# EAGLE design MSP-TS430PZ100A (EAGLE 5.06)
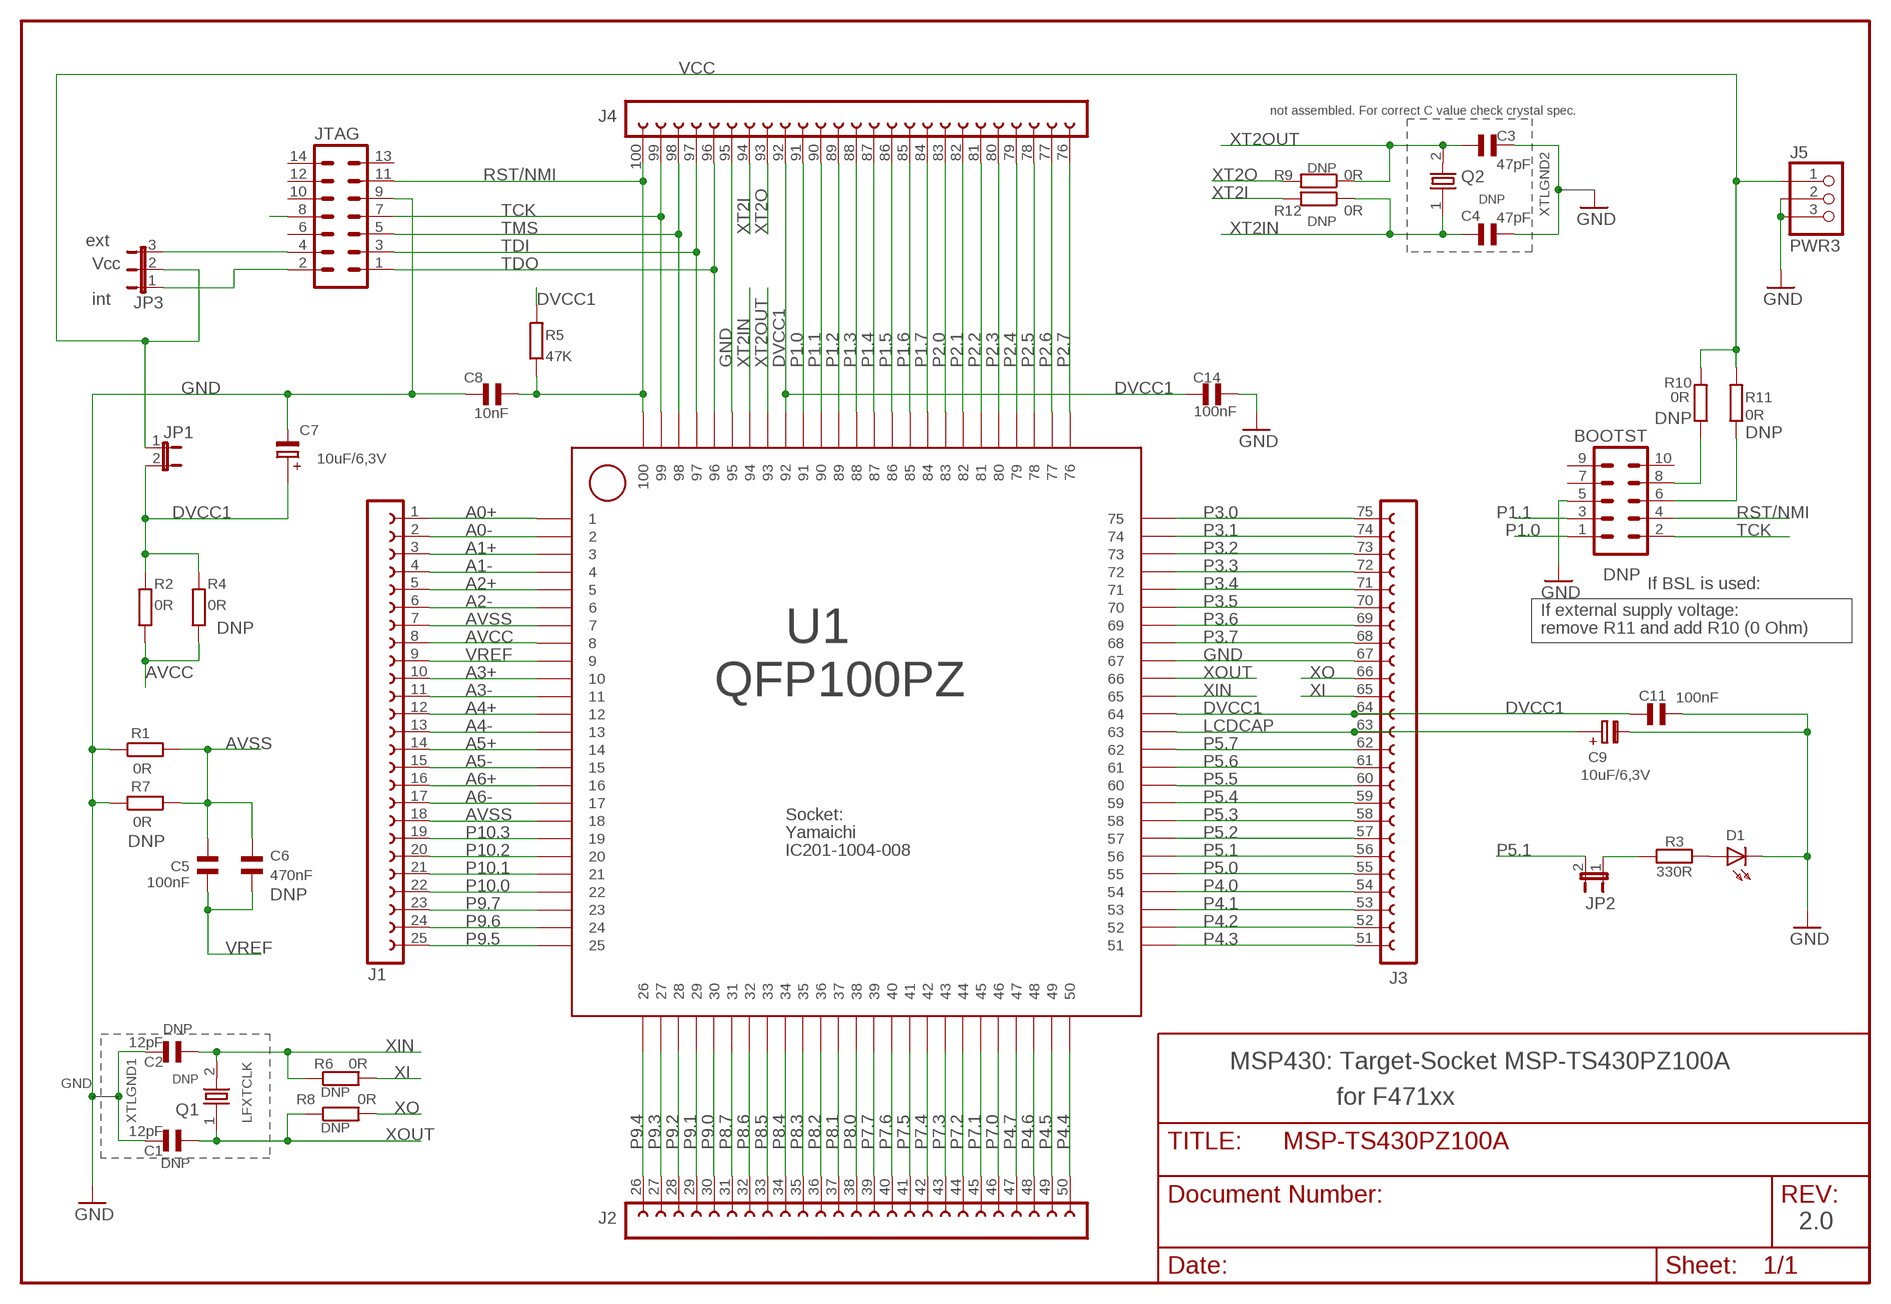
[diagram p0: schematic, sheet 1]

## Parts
BOOTST  ML10  [ML10]
C1  12pF  CSMD0805  [CSMD0805]
C2  12pF  CSMD0805  [CSMD0805]
C3  47pF  CSMD0805  [CSMD0805]
C4  47pF  CSMD0805  [CSMD0805]
C5  100nF  CSMD0805  [CSMD0805]
C6  470nF  CSMD0805  [CSMD0805]
C7  10uF/6,3V  ELKO_1210  [1210ELKO]
C8  10nF  CSMD0805  [CSMD0805]
C9  10uF/6,3V  ELKO_1210  [1210ELKO]
C11  100nF  CSMD0805  [CSMD0805]
C14  100nF  CSMD0805  [CSMD0805]
D1  LED30805  [DIODE_0805]
J1  FE25-1A1  [FE25-1A1]
J2  FE25-1A2  [FE25-1A2]
J3  FE25-1A3  [FE25-1A3]
J4  FE25-1A4  [FE25-1A4]
J5  PWR3  [PWR3]
JP1  JP1E  [JP1]
JP2  JP1E  [JP1]
JP3  JP2ESMALLPAD  [JP2Z]
JTAG  ML14  [ML14]
Q1  HCTC_XTLTCV  [TCV]
Q2  HCTC_XTLTCV  [TCV]
R1  0R  R_0805  [0805]
R2  0R  R_0805  [0805]
R3  330R  R_0805  [0805]
R4  0R  R_0805  [0805]
R5  47K  R_0805  [0805]
R6  0R  R_0805  [0805]
R7  0R  R_0805  [0805]
R8  0R  R_0805  [0805]
R9  0R  R_0805  [0805]
R10  0R  R_0805  [0805]
R11  0R  R_0805  [0805]
R12  0R  R_0805  [0805]
U1  QFP100PZ  [QFP100PZ]

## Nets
A0+: J1.1 U1.P1
A0-: J1.2 U1.P2
A1+: J1.3 U1.P3
A1-: J1.4 U1.P4
A2+: J1.5 U1.P5
A2-: J1.6 U1.P6
A3+: J1.10 U1.P10
A3-: J1.11 U1.P11
A4+: J1.12 U1.P12
A4-: J1.13 U1.P13
A5+: J1.14 U1.P14
A5-: J1.15 U1.P15
A6+: J1.16 U1.P16
A6-: J1.17 U1.P17
AVCC: J1.8 R2.1 R4.1 U1.P8
AVSS: C5.1 C6.1 J1.7 J1.18 R1.2 R7.2 U1.P7 U1.P18
DVCC1: C7.+ C11.1 C14.2 J3.64 J4.92 JP1.2 R2.2 R4.2 R5.2 U1.P64 U1.P92
GND: BOOTST.5 C7.- C8.1 C9.- C11.2 C14.1 D1.K J3.67 J4.95 J5.2 J5.3 JTAG.9 R1.1 R7.1 U1.P67 U1.P95
LCDCAP: C9.+ J3.63 U1.P63
N$1: JP2.1 R3.2
N$7: JP3.1 JTAG.2
N$18: D1.A R3.1
N$23: JP3.3 JTAG.4
N$27: JTAG.8
N$42: BOOTST.8 R10.1
N$49: BOOTST.6 R11.1
P1.0: BOOTST.1 J4.91 U1.P91
P1.1: BOOTST.3 J4.90 U1.P90
P1.2: J4.89 U1.P89
P1.3: J4.88 U1.P88
P1.4: J4.87 U1.P87
P1.5: J4.86 U1.P86
P1.6: J4.85 U1.P85
P1.7: J4.84 U1.P84
P2.0: J4.83 U1.P83
P2.1: J4.82 U1.P82
P2.2: J4.81 U1.P81
P2.3: J4.80 U1.P80
P2.4: J4.79 U1.P79
P2.5: J4.78 U1.P78
P2.6: J4.77 U1.P77
P2.7: J4.76 U1.P76
P3.0: J3.75 U1.P75
P3.1: J3.74 U1.P74
P3.2: J3.73 U1.P73
P3.3: J3.72 U1.P72
P3.4: J3.71 U1.P71
P3.5: J3.70 U1.P70
P3.6: J3.69 U1.P69
P3.7: J3.68 U1.P68
P4.0: J3.54 U1.P54
P4.1: J3.53 U1.P53
P4.2: J3.52 U1.P52
P4.3: J3.51 U1.P51
P4.4: J2.50 U1.P50
P4.5: J2.49 U1.P49
P4.6: J2.48 U1.P48
P4.7: J2.47 U1.P47
P5.0: J3.55 U1.P55
P5.1: J3.56 JP2.2 U1.P56
P5.2: J3.57 U1.P57
P5.3: J3.58 U1.P58
P5.4: J3.59 U1.P59
P5.5: J3.60 U1.P60
P5.6: J3.61 U1.P61
P5.7: J3.62 U1.P62
P7.0: J2.46 U1.P46
P7.1: J2.45 U1.P45
P7.2: J2.44 U1.P44
P7.3: J2.43 U1.P43
P7.4: J2.42 U1.P42
P7.5: J2.41 U1.P41
P7.6: J2.40 U1.P40
P7.7: J2.39 U1.P39
P8.0: J2.38 U1.P38
P8.1: J2.37 U1.P37
P8.2: J2.36 U1.P36
P8.3: J2.35 U1.P35
P8.4: J2.34 U1.P34
P8.5: J2.33 U1.P33
P8.6: J2.32 U1.P32
P8.7: J2.31 U1.P31
P9.0: J2.30 U1.P30
P9.1: J2.29 U1.P29
P9.2: J2.28 U1.P28
P9.3: J2.27 U1.P27
P9.4: J2.26 U1.P26
P9.5: J1.25 U1.P25
P9.6: J1.24 U1.P24
P9.7: J1.23 U1.P23
P10.0: J1.22 U1.P22
P10.1: J1.21 U1.P21
P10.2: J1.20 U1.P20
P10.3: J1.19 U1.P19
RST/NMI: BOOTST.4 C8.2 J4.100 JTAG.11 R5.1 U1.P100
TCK: BOOTST.2 J4.99 JTAG.7 U1.P99
TDI: J4.97 JTAG.3 U1.P97
TDO: J4.96 JTAG.1 U1.P96
TMS: J4.98 JTAG.5 U1.P98
VCC: J5.1 JP1.1 JP3.2 R10.2 R11.2
VREF: C5.2 C6.2 J1.9 U1.P9
XI: J3.65 R6.2
XIN: C2.1 Q1.2 R6.1 U1.P65
XO: J3.66 R8.2
XOUT: C1.1 Q1.1 R8.1 U1.P66
XT2I: J4.94 R12.2
XT2IN: C4.1 Q2.1 R12.1 U1.P94
XT2O: J4.93 R9.2
XT2OUT: C3.1 Q2.2 R9.1 U1.P93
XTLGND1: C1.2 C2.2
XTLGND2: C3.2 C4.2
Unconnected: BOOTST.7 BOOTST.9 BOOTST.10 JTAG.6 JTAG.10 JTAG.12 JTAG.13 JTAG.14

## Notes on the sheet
- not assembled. For correct C value check crystal spec.
- DNP
- DNP
- DNP
- ext
- Vcc
- int
- DNP
- DNP
- DNP
- If BSL is used:
- If external supply voltage:
- DNP | remove R11 and add R10 (0 Ohm)
- Socket:
- Yamaichi
- DNP
- IC201-1004-008
- DNP
- DNP
- MSP430: Target-Socket MSP-TS430PZ100A
- DNP
- GND
- DNP
- for F471xx
- LFXTCLK | DNP
- DNP
- 2.0

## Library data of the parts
BOOTST = con-ml:ML10
C1-C6 C8 C11 C14 = cap:CSMD0805
C7 C9 = smd:ELKO_1210
D1 = MSP430:LED3
J1 = CON-LSTA:FE25-1A1
J2 = CON-LSTA:FE25-1A2
J3 = CON-LSTA:FE25-1A3
J4 = CON-LSTA:FE25-1A4
J5 = MSP430:PWR3
JP1 JP2 = jumper:JP1E: JUMPER
JP3 = jumper:JP2E: JUMPER
JTAG = con-ml:ML14
Q1 Q2 = scrystal:HCTC_XTL
R1-R12 = smd:R_0805
U1 = MSP430:QFP100PZ

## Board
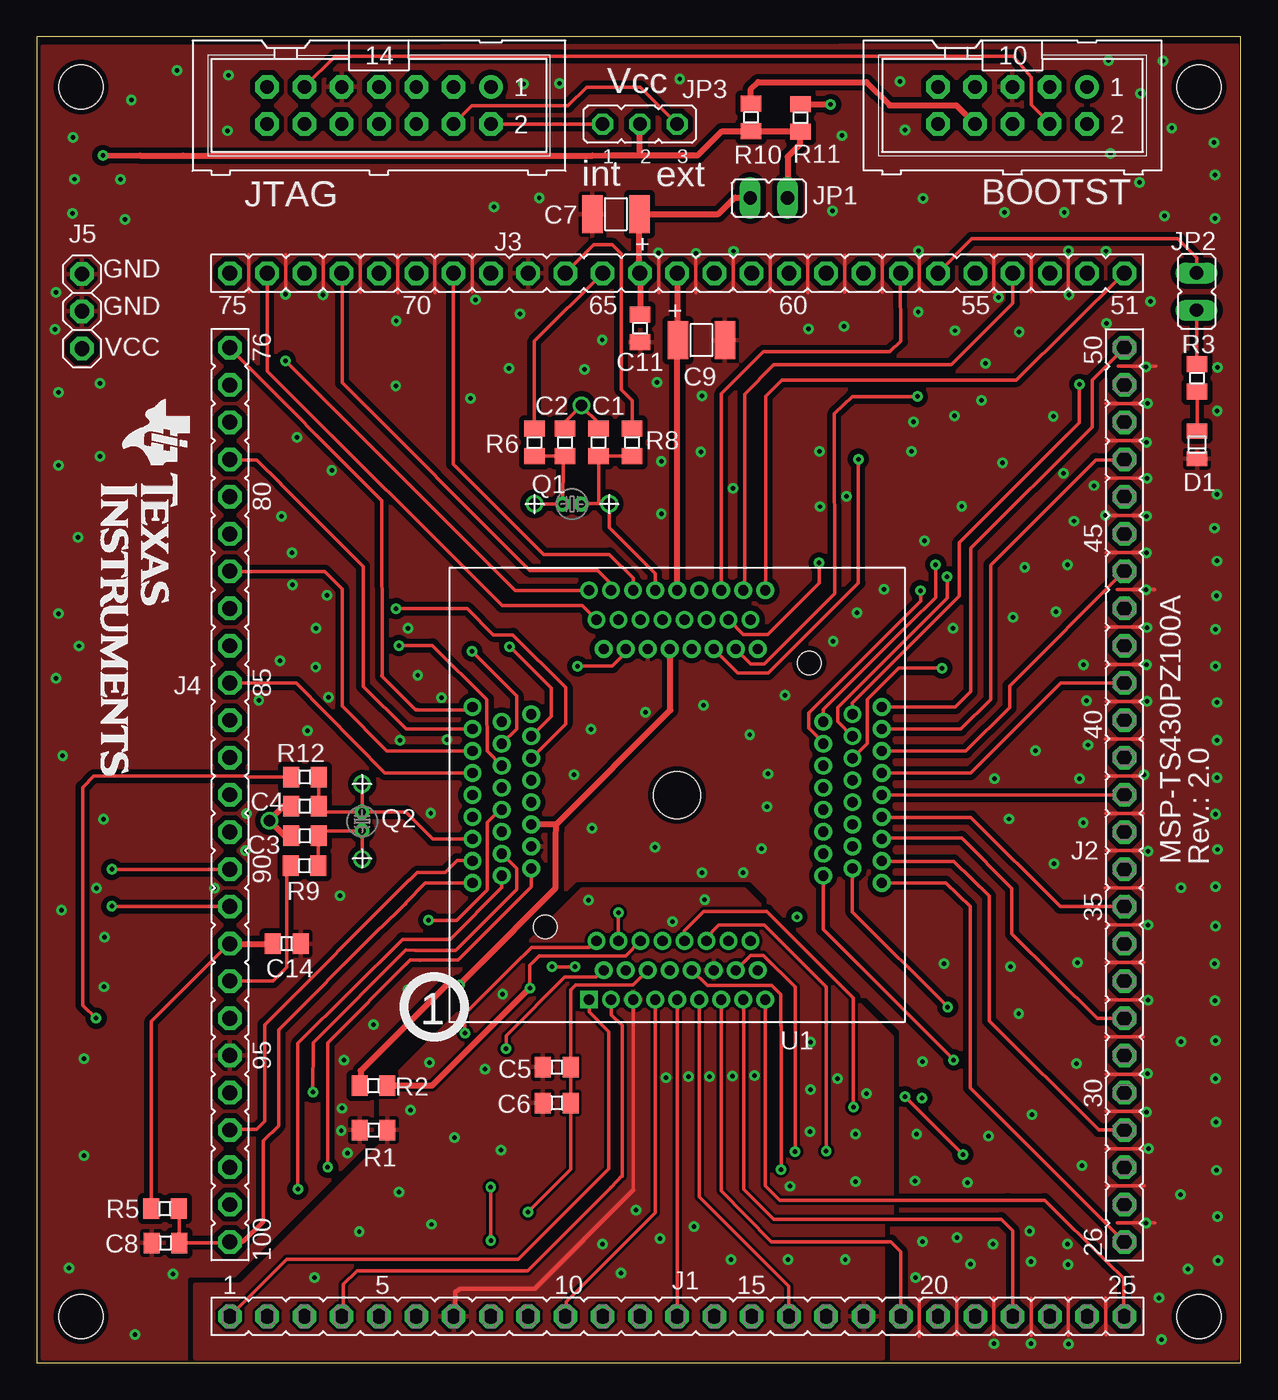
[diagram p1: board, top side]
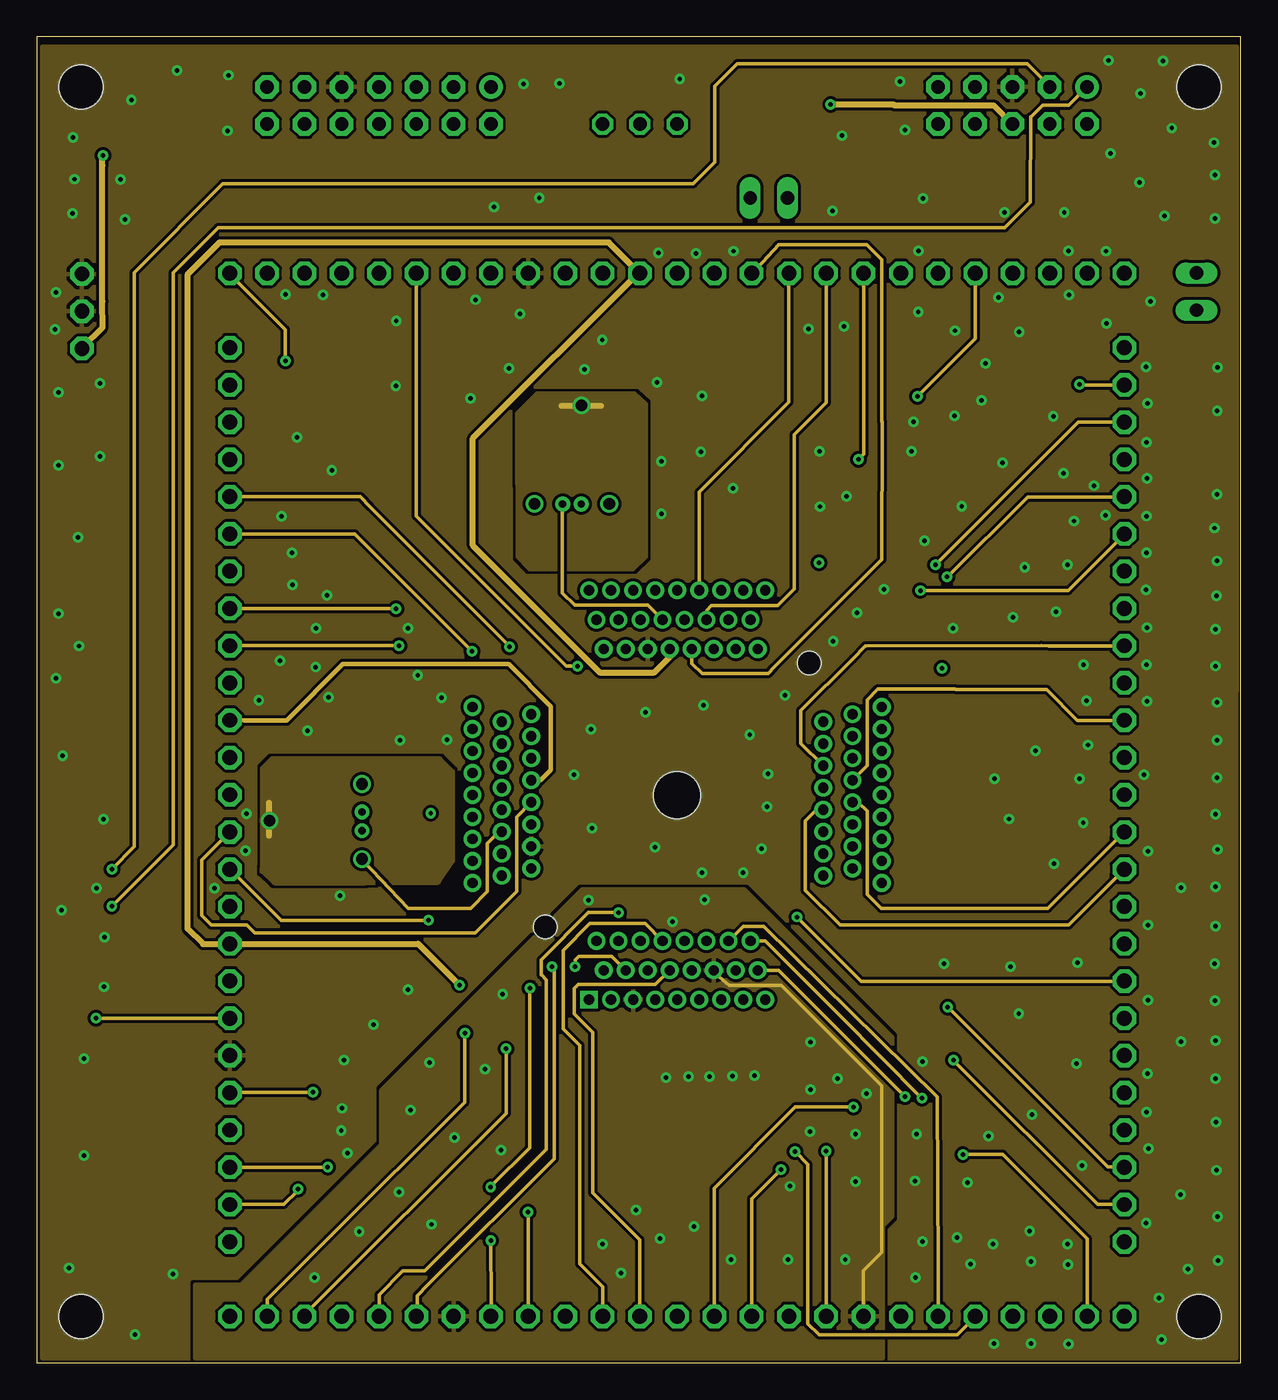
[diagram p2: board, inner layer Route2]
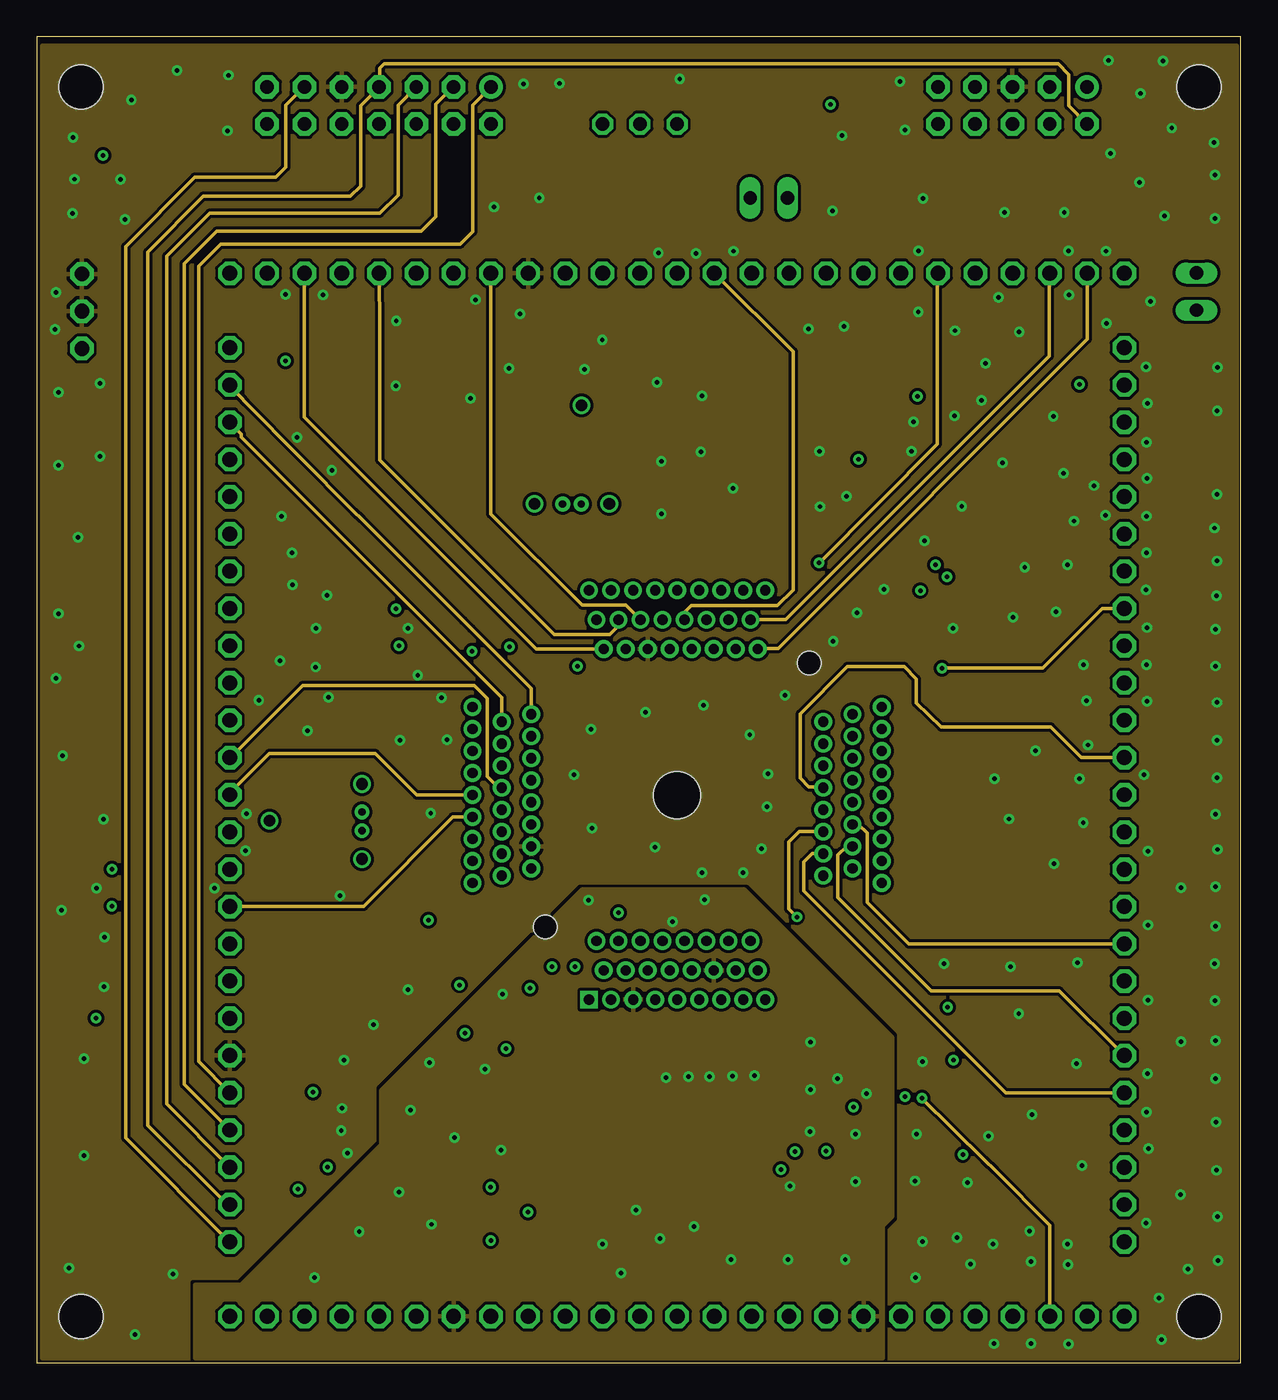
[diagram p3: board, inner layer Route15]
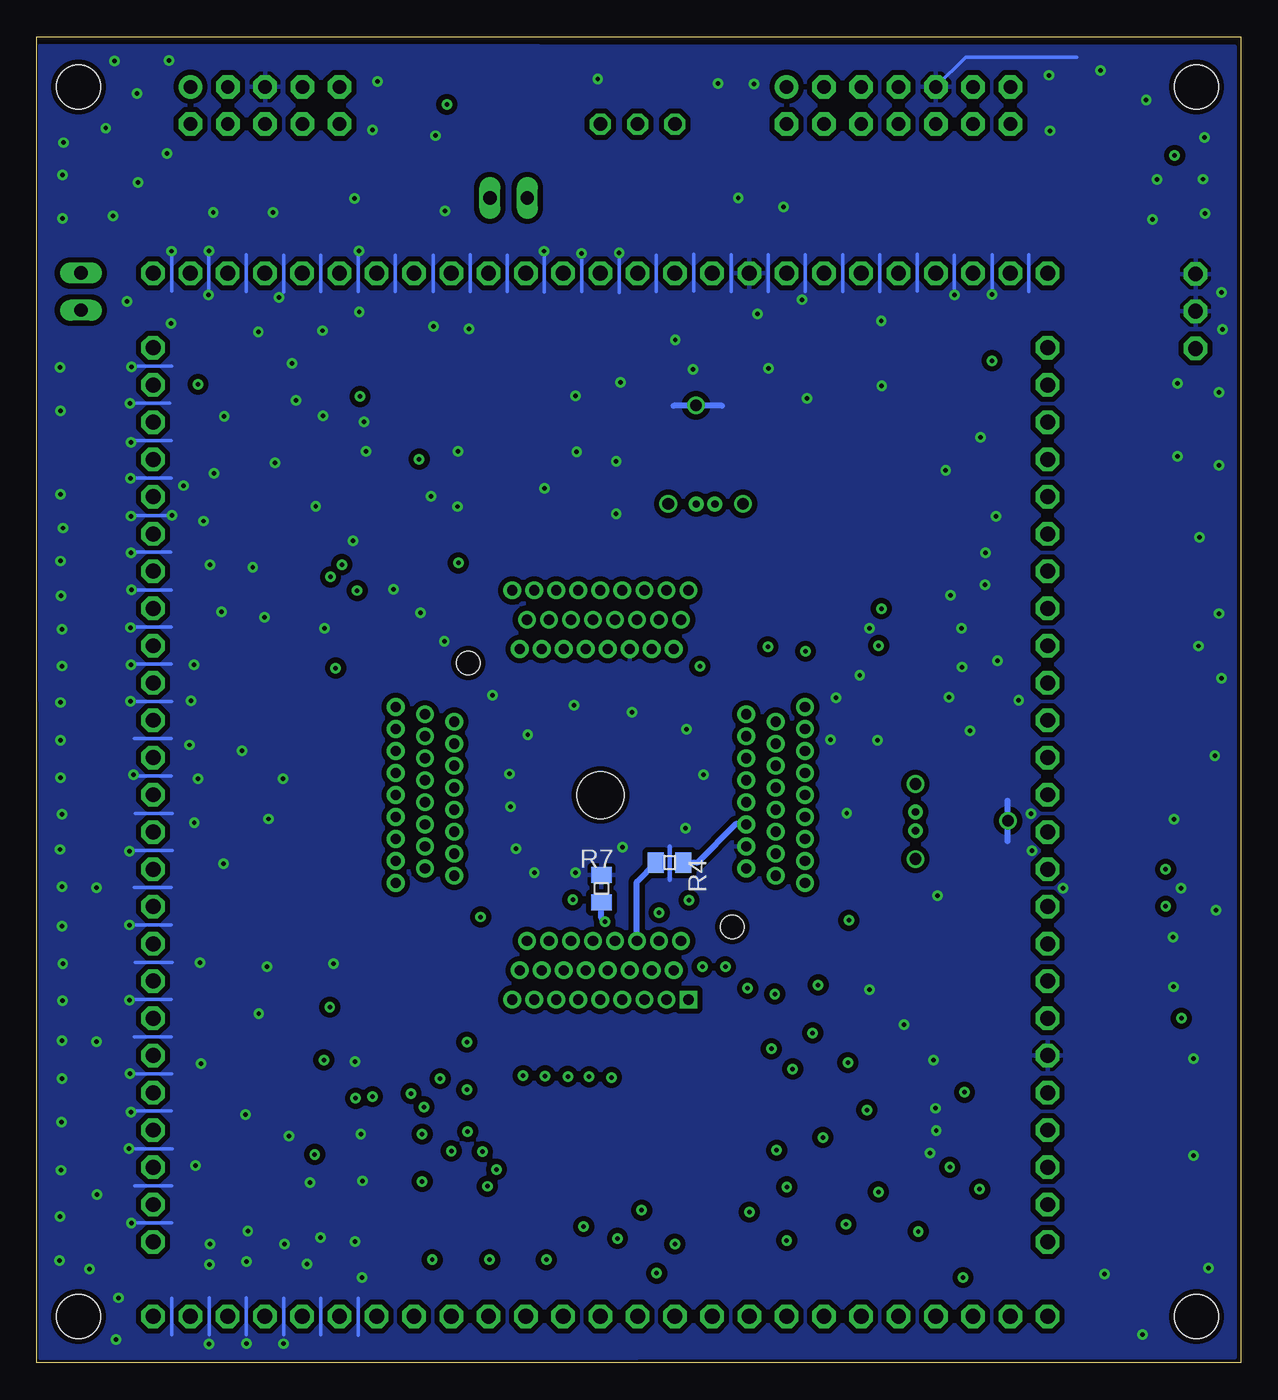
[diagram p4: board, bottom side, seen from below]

Size 82.07 x 90.41 mm. Coordinates in mm from the lower left corner, seen from the top.
Outline: 0,0 82.06,0 82.06,90.41 0,90.41 0,0
Copper layers (1*2+15*16): Top 0.035mm / dielectric 1.5mm / Route2 0.035mm / dielectric 1.5mm / Route15 0.035mm / dielectric 1.5mm / Bottom 0.035mm
Design rules "default *": minimum track width 8mil, minimum drill 12mil, track to track 8mil, track to pad 8mil, pad to pad 8mil, via to via 8mil, smd to smd 8mil, copper to edge 0mil, drill to drill 8mil, minimum pad ring 10mil, minimum via ring 8mil, stop-mask expansion 0mil, vias tented up to drill 0mil, thermal gap 10mil
Holes 3 mm at 3.01,3.17 3.01,86.99 79.21,3.17 79.21,86.99
tRestrict: 2 lines
bRestrict: 2 lines

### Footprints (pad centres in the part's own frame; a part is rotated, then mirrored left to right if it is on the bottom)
ML10 = drill 0.914 pad 1.6 round: 1 -5.08,-1.27 | drill 0.914 pad 1.6 octagon: 2 -5.08,1.27; 3 -2.54,-1.27; 4 -2.54,1.27; 5 0,-1.27; 6 0,1.27; 7 2.54,-1.27; 8 2.54,1.27; 9 5.08,-1.27; 10 5.08,1.27
CSMD0805 = smd 1.092 x 1.397: 1 -0.94,0; 2 0.94,0
1210ELKO = smd 1.397 x 2.591: + 1.6,0; - -1.6,0
DIODE_0805 = smd 1 x 1.4: A -0.94,0; K 0.94,0
FE25-1A1 = drill 1.016 pad 1.6 octagon: 1 -30.48,0; 2 -27.94,0; 3 -25.4,0; 4 -22.86,0; 5 -20.32,0; 6 -17.78,0; 7 -15.24,0; 8 -12.7,0; 9 -10.16,0; 10 -7.62,0; 11 -5.08,0; 12 -2.54,0; 13 0,0; 14 2.54,0; 15 5.08,0; 16 7.62,0; 17 10.16,0; 18 12.7,0; 19 15.24,0; 20 17.78,0; 21 20.32,0; 22 22.86,0; 23 25.4,0; 24 27.94,0; 25 30.48,0
FE25-1A2 = drill 1.016 pad 1.6 octagon: 26 -30.48,0; 27 -27.94,0; 28 -25.4,0; 29 -22.86,0; 30 -20.32,0; 31 -17.78,0; 32 -15.24,0; 33 -12.7,0; 34 -10.16,0; 35 -7.62,0; 36 -5.08,0; 37 -2.54,0; 38 0,0; 39 2.54,0; 40 5.08,0; 41 7.62,0; 42 10.16,0; 43 12.7,0; 44 15.24,0; 45 17.78,0; 46 20.32,0; 47 22.86,0; 48 25.4,0; 49 27.94,0; 50 30.48,0
FE25-1A3 = drill 1.016 pad 1.6 octagon: 51 -30.48,0; 52 -27.94,0; 53 -25.4,0; 54 -22.86,0; 55 -20.32,0; 56 -17.78,0; 57 -15.24,0; 58 -12.7,0; 59 -10.16,0; 60 -7.62,0; 61 -5.08,0; 62 -2.54,0; 63 0,0; 64 2.54,0; 65 5.08,0; 66 7.62,0; 67 10.16,0; 68 12.7,0; 69 15.24,0; 70 17.78,0; 71 20.32,0; 72 22.86,0; 73 25.4,0; 74 27.94,0; 75 30.48,0
FE25-1A4 = drill 1.016 pad 1.6 octagon: 76 -30.48,0; 77 -27.94,0; 78 -25.4,0; 79 -22.86,0; 80 -20.32,0; 81 -17.78,0; 82 -15.24,0; 83 -12.7,0; 84 -10.16,0; 85 -7.62,0; 86 -5.08,0; 87 -2.54,0; 88 0,0; 89 2.54,0; 90 5.08,0; 91 7.62,0; 92 10.16,0; 93 12.7,0; 94 15.24,0; 95 17.78,0; 96 20.32,0; 97 22.86,0; 98 25.4,0; 99 27.94,0; 100 30.48,0
PWR3 = drill 1.016 pad 1.6 octagon: 1 -2.54,0; 2 0,0; 3 2.54,0
JP1 = drill 0.914 long: 1 0,-1.27; 2 0,1.27
JP2Z = drill 0.914 octagon: 1 -2.54,0; 2 0,0; 3 2.54,0
ML14 = drill 0.914 pad 1.6 round: 1 -7.62,-1.27 | drill 0.914 pad 1.6 octagon: 2 -7.62,1.27; 3 -5.08,-1.27; 4 -5.08,1.27; 5 -2.54,-1.27; 6 -2.54,1.27; 7 0,-1.27; 8 0,1.27; 9 2.54,-1.27; 10 2.54,1.27; 11 5.08,-1.27; 12 5.08,1.27; 13 7.62,-1.27; 14 7.62,1.27
TCV = drill 0.5 round: 1 -0.635,0; 2 0.635,0
0805 = smd 1.092 x 1.397: 1 -0.94,0; 2 0.94,0
QFP100PZ = drill 0.7 pad 1 square: P1 -6,-13.95 | drill 0.7 pad 1 round: P2 -5.5,-9.95; P3 -5,-11.95; P4 -4.5,-13.95; P5 -4,-9.95; P6 -3.5,-11.95; P7 -3,-13.95; P8 -2.5,-9.95; P9 -2,-11.95; P10 -1.5,-13.95; P11 -1,-9.95; P12 -0.5,-11.95; P13 0,-13.95; P14 0.5,-9.95; P15 1,-11.95; P16 1.5,-13.95; P17 2,-9.95; P18 2.5,-11.95; P19 3,-13.95; P20 3.5,-9.95; P21 4,-11.95; P22 4.5,-13.95; P23 5,-9.95; P24 5.5,-11.95; P25 6,-13.95; P26 13.95,-6; P27 9.95,-5.5; P28 11.95,-5; P29 13.95,-4.5; P30 9.95,-4; P31 11.95,-3.5; P32 13.95,-3; P33 9.95,-2.5; P34 11.95,-2; P35 13.95,-1.5; P36 9.95,-1; P37 11.95,-0.5; P38 13.95,0; P39 9.95,0.5; P40 11.95,1; P41 13.95,1.5; P42 9.95,2; P43 11.95,2.5; P44 13.95,3; P45 9.95,3.5; P46 11.95,4; P47 13.95,4.5; P48 9.95,5; P49 11.95,5.5; P50 13.95,6; P51 6,13.95; P52 5.5,9.95; P53 5,11.95; P54 4.5,13.95; P55 4,9.95; P56 3.5,11.95; P57 3,13.95; P58 2.5,9.95; P59 2,11.95; P60 1.5,13.95; P61 1,9.95; P62 0.5,11.95; P63 0,13.95; P64 -0.5,9.95; P65 -1,11.95; P66 -1.5,13.95; P67 -2,9.95; P68 -2.5,11.95; P69 -3,13.95; P70 -3.5,9.95; P71 -4,11.95; P72 -4.5,13.95; P73 -5,9.95; P74 -5.5,11.95; P75 -6,13.95; P76 -13.95,6; P77 -9.95,5.5; P78 -11.95,5; P79 -13.95,4.5; P80 -9.95,4; P81 -11.95,3.5; P82 -13.95,3; P83 -9.95,2.5; P84 -11.95,2; P85 -13.95,1.5; P86 -9.95,1; P87 -11.95,0.5; P88 -13.95,0; P89 -9.95,-0.5; P90 -11.95,-1; P91 -13.95,-1.5; P92 -9.95,-2; P93 -11.95,-2.5; P94 -13.95,-3; P95 -9.95,-3.5; P96 -11.95,-4; P97 -13.95,-4.5; P98 -9.95,-5; P99 -11.95,-5.5; P100 -13.95,-6 | hole 3.2: 0,0 | hole 1.6: -9,-9; 9,9

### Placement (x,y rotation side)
BOOTST  66.5,85.72 180 top
C1  38.3,62.77 90 top
C2  36.02,62.76 90 top
C3  18.29,35.93 180 top
C4  18.29,37.95 180 top
C5  35.45,20.16 0 top
C6  35.45,17.72 0 top
C7  39.48,78.33 0 top
C8  8.77,8.18 0 top
C9  45.3,69.72 180 top
C11  41.13,70.54 270 top
C14  17.04,28.58 180 top
D1  79.08,62.58 270 top
J1  43.65,3.17 0 top
J2  74.13,38.73 90 top
J3  43.65,74.29 180 top
J4  13.17,38.73 270 top
J5  3.09,71.7 90 top
JP1  49.9,79.42 90 top
JP2  79.05,73.04 0 top
JP3  41.11,84.45 0 top
JTAG  23.33,85.72 180 top
Q1  36.48,58.55 180 top
Q2  22.17,36.92 270 top
R1  22.96,15.87 0 top
R2  22.97,18.89 180 top
R3  79.09,67.15 90 top
R4  38.93,34.11 0 bottom
R5  8.75,10.51 180 top
R6  33.92,62.75 90 top
R7  43.57,32.33 270 bottom
R8  40.58,62.76 90 top
R9  18.26,33.9 180 top
R10  48.68,84.91 270 top
R11  52.06,84.87 270 top
R12  18.28,39.94 180 top
U1  43.65,38.71 0 top
U$1  [LABEL_2008_TNAMES]  6.31,56.81 270 top

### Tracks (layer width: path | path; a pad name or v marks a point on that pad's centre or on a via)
A0+
  Top 0.254: U1.P1 37.65,23.91 38.99,22.57 38.99,13.23 32.81,7.05 17.06,7.05 13.2,3.2 13.2,3.17 J1.1
A0-  (via drill 0.3)
  Top 0.254: U1.P2 38.17,28.74 38.17,28.73 38.07,28.73 37.66,28.33 33.73,28.33 32.45,27.06 32.45,27.05 29.15,23.75 v29.18,22.48
  Route2 0.254: v29.18,22.48 29.18,17.77 19.83,8.44 15.71,4.32 J1.2
A1+  (via drill 0.3)
  Top 0.254: U1.P3 38.13,26.3 35.99,26.3 31.99,22.31 v31.99,21.41
  Route2 0.254: v31.99,21.41 31.99,20.1 32,19.51 32,17.03 18.27,3.3 18.27,3.19 J1.3
A1-
  Top 0.254: J1.4 20.9,3.3 20.9,5.35 21.83,6.28 33.48,6.28 39.15,11.95 39.14,11.95 39.14,11.96 39.15,11.97 39.89,12.73 39.9,12.72 39.9,22.99 39.16,23.74 39.16,24.31 U1.P4 | J1.4
A2+  (via drill 0.3)
  Top 0.254: U1.P5 39.65,28.74 39.64,28.73 v39.64,30.69
  Route2 0.254: J1.5 23.33,4.64 24.96,6.27 26.46,6.27 34.71,14.55 34.73,26.12 34.38,26.47 34.4,26.45 34.4,27.47 37.58,30.7 38.47,30.7 v39.64,30.69
A2-  (via drill 0.3)
  Top 0.254: v35.13,27 v36.7,27
  Route2 0.254: U1.P6 39.19,27.72 36.95,27.72 36.7,27.46 v36.7,27 | v35.13,27 35.27,26.83 35.27,13.91 26.7,5.34 25.94,4.59 25.95,3.9 25.89,3.85 25.89,3.19 J1.6
A3+
  Top 0.254: 35.9,3.17 35.85,3.12 | 35.9,3.17 J1.10 | 35.9,3.17 36.1,3.37 36.1,4.17 42.15,10.22 U1.P10
A3-
  Route2 0.254: U1.P11 41.47,29.94 37.71,29.94 35.88,28.11 35.88,22.75 36.99,21.64 36.99,6.75 38.57,5.18 J1.11
A4+
  Route2 0.254: U1.P12 42.17,25.79 36.9,25.79 36.65,25.53 36.65,23.79 37.91,22.52 37.91,19.83 37.89,19.42 37.91,19.08 37.91,11.6 41.11,8.37 J1.12
A4-
  Top 0.254: J1.13 U1.P13
A5+  (via drill 0.3)
  Top 0.254: U1.P14 44.15,29.45 45.48,30.78 49.77,30.78 55.66,24.89 v55.66,17.45
  Route2 0.254: v55.66,17.45 51.7,17.45 46.16,11.91 46.16,4.11 46.19,3.75 J1.14
A5-  (via drill 0.3)
  Top 0.254: U1.P15 45.69,25.72 50.11,25.72 50.72,25.12 50.72,23 50.73,22.99 v50.73,13.19
  Route2 0.254: J1.15 48.73,4.31 48.73,11.19 v50.73,13.19
A6+
  Top 0.254: U1.P16 45.15,11.32 51.27,5.2 J1.16
A6-  (via drill 0.3)
  Top 0.254: v53.81,14.45 53.81,25.62 49.59,29.84 46.5,29.84 45.61,28.95 45.65,28.91 U1.P17
  Route2 0.254: J1.17 v53.81,14.45
AVCC  (via drill 0.3)
  Top 0.254: U1.P8 40.14,27.75 34.25,27.75 34.25,27.74 33.78,27.27 33.78,27.26 33.62,27.09 v33.62,25.53 | v30.95,8.35 v30.95,11.99
  Top 0.406: v33.62,25.53 33.58,25.53 26.94,18.89 R2.1
  Route2 0.254: v33.62,25.53 33.62,24.23 33.61,24.02 33.61,14.67 30.96,12.02 v30.95,11.99 | J1.8 30.97,4.11 v30.95,8.35
  Bottom 0.406: U1.P8 41.16,32.79 R4.1
AVSS  (via drill 0.3 pad 0.3)
  Top 0.254: 28.52,3.46 28.35,3.29 28.41,3.23 J1.7 | U1.P7 40.65,24.39 40.65,24.31 40.65,24.21 40.65,11.79
  Top 0.305: 40.65,11.79 33.94,5.06 28.88,5.06 28.52,4.85 28.52,3.46
  Route2 0.254: 46.53,26.3 U1.P18 | 46.53,26.3 U1.P18 | 46.53,26.3 47.19,25.73 50.75,25.73 57.58,18.89 57.58,7.54 56.32,6.27 56.32,4.37 J1.18
  Bottom 0.406: v43.34,30.07 43.34,30.09 43.57,30.32 R7.2
  other vias: 26.91,9.44 31.64,14.5 30.54,20.04 28.49,15.36 24.7,11.65 18.94,5.81 21.98,8.96 25.49,17.24 26.78,20.47 31.76,25.14 37.6,31.54 45.53,31.57 42.89,19.45 44.41,19.5 45.86,19.53 47.41,19.55 48.91,19.58 52.74,21.86 52.74,18.61 52.69,15.77 54.57,19.38 56.55,18.36 55.79,15.59 55.79,12.36 51.35,12.03 44.79,9.29 42.48,8.48 39.81,6.12 38.57,8.1 40.83,10.41 47.33,7.03 51.19,7.03 55.11,7.03
  pour Top: 10.81,5.3 13.93,5.3 23.48,14.85 23.48,18.56 37.2,32.28 48.22,32.28 58.28,22.22 58.28,9.98 57.65,9.34 57.65,0.3 10.81,0.3
  pour Route2: 10.81,5.3 13.93,5.3 23.48,14.85 23.48,18.56 37.2,32.28 48.22,32.28 58.31,22.19 58.31,10 57.65,9.34 57.65,0.33 10.81,0.33
  pour Route15: 10.81,5.3 13.93,5.3 23.48,14.85 23.48,18.56 37.2,32.28 48.22,32.28 58.31,22.19 58.31,10 57.65,9.34 57.65,0.3 10.81,0.3
DVCC1  (via drill 0.3)
  Top 0.254: U1.P92 | 22.09,19.02 22.02,18.96 R2.2 | J4.92 13.14,28.57 13.12,28.59 7.81,23.29 R5.2
  Top 0.406: 35.4,36.7 35.38,35.7 35.38,32.39 29.79,26.76 v28.81,25.76 27.94,25.76 22.09,19.91 22.09,19.02 | 35.4,36.7 34.35,36.72 U1.P92 | C11.1 41.13,74.23 41.13,74.24 41.11,74.27 J3.64 41.11,74.52 41.08,74.55 C7.+ 46.47,78.33 47.59,79.45 48.43,79.45 48.45,79.47 48.5,79.42 JP1.2 | C14.2 J4.92 | U1.P64 43.19,48.62 43.19,44.5 35.4,36.7
  Route2 0.406: J4.92 26,28.57 v28.81,25.76 | U1.P64 43.15,48.14 42.05,47.04 38.42,47.04 29.73,55.72 29.73,63.04 40.98,74.29 J3.64 41.06,74.34 41.03,74.34 39,76.37 12.46,76.37 10.27,74.19 10.27,29.61 11.34,28.54 13.04,28.54
  Bottom 0.406: R4.2 37.05,34.08 34.43,36.72 33.77,36.72 33.76,36.71 U1.P92
GND  (via drill 0.3)
  Top 0.254: 72.86,65.4 75.4,65.4 | 73.72,67.97 76.26,67.97 | 72.94,62.86 75.48,62.86 | 72.89,60.32 75.42,60.32 | 72.96,57.78 75.5,57.78 | 72.91,55.24 75.45,55.24 | 73.65,52.73 76.19,52.73 | 72.89,50.16 75.42,50.16 | 72.94,47.62 75.48,47.62 | 72.91,45.08 75.45,45.08 | 72.83,42.54 75.38,42.54 | 72.89,40.02 75.42,40.02 | 72.86,37.46 75.4,37.46 | 72.89,34.92 75.42,34.92 | 72.83,32.38 75.38,32.38 | 72.96,29.84 75.5,29.84 | 72.91,27.3 75.45,27.3 | 72.89,24.76 75.42,24.76 | 72.86,22.22 75.4,22.22 | 72.89,19.68 75.42,19.68 | 72.89,17.14 75.42,17.14 | 72.91,14.6 75.45,14.6 | 72.94,12.06 75.48,12.06 | 73.65,9.54 76.19,9.54 | 72.86,1.9 72.86,4.44 | 70.32,1.88 70.32,4.41 | 67.78,1.88 67.78,4.41 | 65.24,1.9 65.24,4.44 | 62.7,1.9 62.7,4.44 | 60.16,1.82 60.16,4.36 | 14.44,73.02 14.44,75.56 | 16.98,73.02 16.98,75.56 | 19.52,72.92 19.52,75.46 | 22.06,73 22.06,75.53 | 24.6,72.97 24.6,75.51 | 27.14,72.97 27.14,75.51 | 29.68,73.02 29.68,75.56 | 42.38,72.97 42.38,75.51 | 44.92,72.97 44.92,75.51 | 47.46,73.12 47.46,75.66 | 50,73.02 50,75.56 | 52.54,72.97 52.54,75.51 | 55.08,73 55.08,75.53 | 57.62,73 57.62,75.53 | 60.16,73.07 60.16,75.61 | 65.24,73 65.24,75.53 | 67.78,73.05 67.78,75.59 | 70.32,73.05 70.32,75.59
  Bottom 0.254: JTAG.9 18.75,89.03 11.17,89.03 | v72.86,57.78 75.38,57.78 | 72.94,55.27 75.45,55.27 | 72.91,60.32 75.42,60.32 | 72.91,62.88 75.42,62.88 | 72.89,52.7 75.4,52.7 | 72.89,50.16 75.4,50.16 | 72.91,47.64 75.42,47.64 | 72.86,45.08 75.38,45.08 | 72.89,42.56 75.4,42.56 | 72.89,40.02 75.4,40.02 | 72.83,37.46 75.35,37.46 | 72.83,34.92 75.35,34.92 | 72.91,32.41 75.42,32.41 | 72.91,29.84 75.42,29.84 | 72.83,27.3 75.35,27.3 | 72.89,24.78 75.4,24.78 | 72.89,22.22 75.4,22.22 | 72.86,19.7 75.38,19.7 | 72.89,17.16 75.4,17.16 | 72.83,14.6 75.35,14.6 | 72.86,12.06 75.38,12.06 | 72.86,9.54 75.38,9.54 | 72.86,1.9 72.86,4.41 | 70.32,1.92 70.32,4.44 | 67.78,1.92 67.78,4.44 | 65.24,1.9 65.24,4.41 | 62.7,1.9 62.7,4.41 | 60.14,1.88 60.14,4.39 | 14.44,73.05 14.44,75.56 | 16.95,73.05 16.95,75.56 | 19.52,73.02 19.52,75.53 | 22.06,73.07 22.06,75.59 | 24.6,73.05 24.6,75.56 | 27.14,73.05 27.14,75.56 | 29.68,73.05 29.68,75.56 | 32.22,73.05 32.22,75.56 | 34.73,73.05 34.73,75.56 | 37.3,73.07 37.3,75.59 | 39.84,73.02 39.84,75.53 | 42.35,72.97 42.35,75.48 | 44.92,73.02 44.92,75.53 | 47.46,73 47.46,75.51 | 50,73.02 50,75.53 | 52.52,73.05 52.52,75.56 | 55.05,73.02 55.05,75.53 | 57.62,73.02 57.62,75.53 | 60.16,73.05 60.16,75.56 | 62.7,73.02 62.7,75.53 | 65.24,73 65.24,75.51 | 67.78,73.05 67.78,75.56 | 70.34,73 70.34,75.51 | 72.86,73.07 72.86,75.59 | 73.01,65.42 75.53,65.42 | 72.86,67.94 75.38,67.94
  Bottom 0.305: 38.93,32.91 38.93,35.2
  Bottom 0.406: 35.36,65.25 38.66,65.25 | 15.89,35.58 15.89,38.32
  other vias: 48.6,42.83 53.4,58.38 19.02,47.44 17.44,53.03 19.77,52.32 66.27,37.08 41.49,44.34 60.08,71.64 69.28,64.52 72.06,59.81 47.44,59.61 25.97,46.89 27.58,45.34 29.91,72.48 24.51,71.03 60.37,8.27 59.88,5.83 62.72,8.55 65.17,8.11 63.64,6.74 67.68,8.98 67.76,6.89 63.44,12.28 70.25,8.1 70.3,6.71 64.86,15.47 65.25,1.3 67.77,1.33 70.33,1.27 76.66,1.58 76.49,4.43 75.62,9.52 77.96,11.46 80.41,13.13 80.47,9.97 80.52,6.97 78.46,6.38 59.98,15.58 75.64,17.11 75.78,14.62 80.38,16.4 80.35,19.36 80.35,21.96 75.7,19.7 75.74,24.72 75.74,29.85 80.32,24.69 80.29,27.23 80.35,29.77 60.37,20.55 37.79,43.2 36.62,40.1 45.35,33.43 48.15,33.42 49.41,35.04 49.78,37.92 49.83,40.15 51.01,45.51 45.44,44.82 80.35,32.46 75.75,34.89 80.46,35 80.35,37.4 80.44,39.88 80.44,42.45 80.44,45.02 75.47,40.08 75.67,45.11 75.64,47.59 75.67,50.13 75.61,52.7 75.64,55.24 80.35,47.51 80.35,50.02 54.29,49.19 55.9,51.14 57.76,52.75 75.64,57.73 75.67,60.3 69.97,60.66 60.5,56.03 63.05,58.4 65.82,61.35 62.57,64.55 64.4,65.63 64.65,68.14 59.77,64.16 59.63,62.15 75.64,62.75 75.7,65.4 75.61,67.92 80.47,67.86 80.46,64.89 80.43,59.2 75.92,72.38 72.92,70.86 70.36,72.8 65.54,72.64 62.58,70.37 70.33,75.82 72.87,75.79 80.41,52.3 80.27,56.91 80.43,54.66 80.29,78.02 76.85,78.19 55.2,59.08 53.34,62.13 73.18,82.45 80.29,80.98 80.24,83.19 77.36,84.17 75.24,86.54 73.04,88.8 76.76,88.75 75.16,80.48 70.03,78.43 65.96,78.43 60.4,79.38 54.88,83.66 59.19,84.06 58.85,87.36 44.93,75.62 42.36,75.68 47.5,75.79 60.08,75.82 33.17,87.19 35.62,87.22 13.08,87.78 12.99,84 9.55,88.12 6.45,86.09 2.47,83.55 2.58,80.7 2.44,78.36 6.01,77.94 5.71,80.69 19.51,72.8 24.47,66.59 16.97,72.83 17.74,63.11 20.11,60.85 19.05,50.07 16.59,47.85 15.14,45.16 24.75,42.44 27.96,42.47 19.9,45.38 25.31,50.07 1.48,66.16 1.48,61.19 2.83,56.27 1.48,51.08 1.31,46.68 1.25,70.45 1.31,72.99 4.3,66.78 4.3,61.81 2.9,48.87 1.78,41.38 1.69,30.86 9.3,6.06 2.19,6.45 6.71,1.94 77.99,21.89 77.99,32.39 3.23,20.75 3.23,14.12 21.19,14.3 20.76,15.83 20.81,17.35 20.93,20.63 22.94,23.07 25.3,25.43 4.63,29.03 4.58,25.63 4.55,37.06 32.93,71.52 32.19,67.81 29.58,65.76 17.41,55.21 16.68,57.7 31.18,78.81 34.25,79.42 38.54,69.74 37.33,67.74 42.28,66.85 43.83,87.52 54.22,78.53 45.34,65.94 45.26,62.1 52.61,70.49 55.03,70.67 66.96,70.29 42.57,61.47 42.57,57.89 70.69,57.39 67.34,54.24 70.26,54.42 66.55,50.84 69.47,51.19 71.35,47.58 71.56,45.15 71.66,42.12 65.28,39.84 68.08,41.74 71.07,39.84 69.32,34.03 71.33,36.83 70.94,27.27 61.83,27.22 66.37,27.02 66.93,23.79 70.87,20.39 59.85,12.41 67.83,16.93 71.23,13.45 37.84,36.44 42.15,35.17 62.46,50.07 14.31,37.45 14.22,34.9 4.07,32.36 12.12,32.36 18.45,43.1 20.67,31.85 26.86,37.48
  pour Top (isolate 0.356, rank 2): 0.41,0.33 81.79,0.3 81.8,64.38 81.8,89.82 0.41,89.72
  pour Bottom (isolate 0.356, rank 2): 0.42,0.38 81.79,0.3 81.84,89.8 13.8,89.72 0.42,89.72
  pour Route15 (rank 2): 81.8,0.3 0.39,0.33 0.39,89.81 81.8,89.78
  pour Route2 (rank 2): 81.75,0.3 0.39,0.3 0.39,89.73 81.8,89.73 81.75,1.72
LCDCAP
  Top 0.254: 43.65,69.59 43.7,69.64 C9.+ | 43.7,74.29 J3.63
  Top 0.406: U1.P63 43.65,69.59 | C9.+ 43.7,74.29
N$1
  Top 0.254: R3.2 79.09,68 79.06,67.97 79.05,67.97 JP2.1
N$7
  Top 0.254: JTAG.2 JP3.1
N$18
  Top 0.254: 79.08,63.44 | D1.A 79.08,63.44 | R3.1 79.09,63.45 79.08,63.44
N$23
  Top 0.254: JTAG.4 29.66,85.69 36.21,85.69 37.48,86.97 41.13,86.97 JP3.3
N$42
  Top 0.406: BOOTST.8 62.68,85.74 58.14,85.74 56.55,87.32 49.16,87.32 48.68,86.84 R10.1
N$49  (via drill 0.3)
  Top 0.254: v54.1,85.81 v54.12,85.8
  Top 0.406: R11.1 v54.1,85.81
  Route2 0.406: BOOTST.6 65.23,85.73 58.45,85.73 58.38,85.8 v54.12,85.8
P1.0  (via drill 0.3)
  Top 0.254: J4.91 13.04,30.98 12.92,31.11 v5.12,31.12
  Route2 0.254: v5.12,31.12 9.31,35.32 9.31,74.34 12.38,77.39 65.98,77.39 67.73,79.14 67.75,84.92 67.74,84.93 67.74,84.95 67.78,84.95 68.57,85.74 70.33,85.74 BOOTST.1
  Route15 0.254: U1.P91 29.56,37.21 29.55,37.21 28.36,37.21 22.28,31.12 13.31,31.12 13.3,31.11 J4.91
P1.1  (via drill 0.3)
  Top 0.254: U1.P90 31.58,37.71 30.72,36.85 30.72,32.25 28.64,30.17 v26.71,30.17 | v5.12,33.65 J4.90
  Route2 0.254: J4.90 13.2,33.65 16.68,30.17 v26.71,30.17 | v5.12,33.65 6.64,35.2 6.64,74.34 12.69,80.39 44.74,80.39 46.22,81.86 46.22,87.04 47.74,88.56 67.48,88.56 67.51,88.56 69.04,87.03 BOOTST.3
P1.2
  Route2 0.254: U1.P89 33.68,38.21 32.7,37.23 32.7,32.13 29.88,29.31 14.87,29.31 14.31,29.86 11.9,29.86 11.27,30.5 11.27,34.28 J4.89
P1.3
  Route15 0.254: U1.P88 25.91,38.71 23.08,41.55 15.86,41.55 13.17,38.86 J4.88
P1.4
  Route15 0.254: U1.P87 31.46,39.21 30.7,39.97 30.7,45.28 29.81,46.17 18.12,46.17 13.22,41.27 J4.87
P1.5
  Route2 0.305: U1.P86 34.32,39.71 35.04,40.43 35.04,44.75 32.18,47.63 20.87,47.63 17.05,43.78 14.11,43.78 J4.86
P1.6
  Top 0.254: U1.P85 23.72,40.21 17.7,46.34 13.46,46.34 13.45,46.35 J4.85
P1.7  (via drill 0.3)
  Top 0.254: v24.68,48.89 26.97,48.91 30.68,45.23 30.69,41.71 U1.P84
  Route2 0.254: J4.84 24.25,48.89 v24.68,48.89
P2.0  (via drill 0.3)
  Top 0.254: v24.5,51.42 29.33,51.42 31.11,49.63 32.45,49.63 36.05,46.03 36.05,43.56 U1.P83
  Route2 0.254: J4.83 24,51.43 v24.5,51.42
P2.1
  Top 0.254: U1.P82 23.87,41.72 20.82,44.79 20.82,52.77 19.65,53.94 13.38,53.94 13.35,53.97 J4.82
P2.2  (via drill 0.3)
  Top 0.254: v29.67,48.51 32.71,45.47 32.71,43.23 U1.P81 | U1.P81 | U1.P81
  Route2 0.254: J4.81 21.67,56.51 v29.67,48.51
P2.3  (via drill 0.3)
  Top 0.254: U1.P80 35.06,44.07 35.06,46.02 33.6,47.49 33.59,47.49 v32.23,48.82
  Route2 0.254: J4.80 22.04,59.05 22.72,58.35 29.99,51.08 v32.23,48.82
P2.4
  Top 0.254: U1.P79 25.18,43.21 22.24,46.12 22.24,54.29 22.2,54.34 16.62,59.91 16.62,59.93 15,61.55 13.26,61.55 13.22,61.59 J4.79
P2.5
  Route15 0.254: U1.P78 31.7,45.37 13.96,63.11 13.96,63.32 13.17,64.1 J4.78
P2.6
  Route15 0.254: U1.P77 33.7,45.99 29.63,50.06 29.07,50.62 22.15,57.53 21.62,58.05 14.24,65.45 J4.77
P2.7
  Top 0.254: 13.11,69.21 12.99,69.34 | 13.11,69.21 J4.76 | 13.11,69.21 23.53,58.8 23.55,46.92 23.53,46.84 25.84,44.52 | U1.P76 29.2,44.52 25.84,44.52 | 25.84,44.52 25.92,44.55
P3.0  (via drill 0.3)
  Top 0.254: U1.P75 32.61,52.66 v16.95,68.32
  Route2 0.254: J3.75 13.17,74.21 16.95,70.43 v16.95,68.32
P3.1
  Top 0.254: U1.P74 37.18,51.63 35.09,51.63 31.71,51.63 16.09,67.25 15.71,67.63 J3.74
P3.2
  Route15 0.254: J3.73 18.25,64.48 34.04,48.65 37.95,48.66 38.54,48.66 38.55,48.66 U1.P73
P3.3
  Top 0.254: U1.P72 39.15,53.11 38.24,54.02 33.62,54.02 20.81,66.82 20.81,74.14 20.74,74.21 20.79,74.27 J3.72
P3.4
  Route15 0.254: U1.P71 39.64,50.52 39.64,50.23 39.07,49.67 35.28,49.65 23.38,61.55 23.38,71.87 23.36,72.84 J3.71
P3.5  (via drill 0.3)
  Top 0.254: U1.P70 40.15,48.41 39.23,47.49 v36.87,47.49
  Route2 0.254: v36.87,47.49 36.08,47.49 35.4,48.18 25.87,57.73 J3.70
P3.6
  Top 0.254: U1.P69 40.65,53.49 39.03,55.11 34.56,55.11 28.38,61.28 28.38,74.14 28.41,74.16 J3.69
P3.7
  Route15 0.254: U1.P68 40.16,51.65 37.19,51.65 30.96,57.88 30.96,72.22 J3.68
P4.0
  Top 0.254: 66.66,74.29 66.67,74.3 | 66.66,74.29 J3.54 | 66.66,74.29 66.53,74.16 66.53,72.25 62.31,68.05 50.23,68.05 48.25,66.04 48.25,52.79 48.15,52.69 U1.P54
P4.1
  Route15 0.254: U1.P53 51.06,50.66 69.02,68.63 69.02,73.91 69.05,73.93 J3.53
P4.2
  Route15 0.254: J3.52 71.59,73.82 71.59,73.57 71.59,71.86 71.59,69.78 50.53,48.69 49.69,48.69 49.68,48.69 49.18,48.69 U1.P52
P4.3
  Top 0.254: J3.51 66.78,67.01 50.78,67.01 49.68,65.89 49.68,52.72 49.62,52.66 | 49.62,52.66 49.62,52.65 | U1.P51 49.62,52.66
P4.4
  Top 0.254: U1.P50 62.61,44.71 63.65,45.75 63.65,55.56 71.93,63.81 71.93,67 74.15,69.21 | 74.15,69.21 74.27,69.34 | 74.15,69.21 J2.50
P4.5  (via drill 0.3)
  Top 0.254: v71.07,66.71 71.07,64.12 62.89,55.93 62.89,55.88 62.87,55.87 62.87,52.27 55.6,45 U1.P49
  Route2 0.254: v71.07,66.71 71.11,66.67 J2.49
P4.6  (via drill 0.3)
  Top 0.254: U1.P48 53.6,44.54 59.48,50.4 61.27,52.19 v61.27,54.42 61.26,54.43
  Route2 0.254: v61.27,54.42 70.98,64.13 J2.48
P4.7
  Top 0.254: U1.P47 62.99,43.21 65.02,45.24 65.02,54.4 72.17,61.55 74.09,61.55 J2.47
P5.0  (via drill 0.3)
  Top 0.254: U1.P55 48.67,47.64 49.59,47.64 54.38,52.46 54.37,64.71 55.57,65.88 v60.03,65.88
  Route2 0.254: v60.03,65.88 63.97,69.82 J3.55
P5.1  (via drill 0.3)
  Top 0.254: U1.P56 48.15,49.67 49.84,49.67 53.33,53.16 v53.33,54.53 | JP2.2 79.05,75.34 77.76,76.63 63.72,76.63 61.43,74.34 J3.56
  Route15 0.254: v53.33,54.53 61.39,62.62 61.39,74.15 61.38,74.16 61.43,74.21 J3.56
P5.2
  Top 0.254: J3.57 58.89,74.28 58.93,74.23 58.86,74.16 58.89,69.65 58.15,68.93 49.53,68.93 46.67,66.07 46.67,52.72 46.65,52.7 U1.P57
P5.3  (via drill 0.3)
  Top 0.254: U1.P58 47.79,47.03 49.84,47.03 56,53.18 v56,61.6
  Route2 0.254: v56,61.6 56.35,61.96 J3.58
P5.4
  Route2 0.254: U1.P59 45.65,51.3 45.99,51.63 50.51,51.63 51.63,52.75 51.63,63.29 53.81,65.48 J3.59
P5.5
  Route2 0.254: U1.P60 45.15,59.38 51.27,65.5 J3.60
P5.6
  Route2 0.254: U1.P61 44.65,47.68 45.35,46.98 49.87,46.98 50.25,47.45 57.59,54.77 57.59,54.78 57.62,64.08 57.62,64.16 57.61,64.16 57.61,75.19 56.58,76.22 50.59,76.22 49.49,75.04 48.84,74.39 48.83,74.39 J3.61
P5.7
  Route15 0.254: U1.P62 44.15,51.17 44.62,51.63 50.48,51.63 51.55,52.7 51.55,68.93 J3.62
P7.0  (via drill 0.3)
  Top 0.254: U1.P46 54.58,43.73 54.58,44.69 59.55,49.64 62.05,52.13 62.05,53.53 v62.04,53.58
  Route2 0.254: v62.04,53.58 67.55,59.04 74.09,59.04 74.11,59.02 J2.46
P7.1  (via drill 0.3)
  Top 0.254: U1.P45 53.6,42.28 52.61,43.27 52.61,44.32 57.04,48.74 57.04,48.73 60.24,51.93 60.25,52.62 v60.22,52.65
  Route2 0.254: v60.22,52.65 60.95,52.65 70.31,52.65 73.57,55.94 73.58,55.94 74.13,56.48 J2.45
P7.2
  Top 0.254: U1.P44 63.33,41.71 66.3,44.69 66.3,44.68 66.31,44.67 66.31,46.15 J2.44
P7.3  (via drill 0.3)
  Top 0.254: U1.P43 56.61,42.22 56.61,45.21 58.77,47.36 v61.69,47.36
  Route15 0.254: v61.69,47.36 68.56,47.36 72.63,51.44 73.94,51.44 73.95,51.43 J2.43
P7.4
  Route2 0.254: U1.P42 52.09,42.23 52.09,44.46 55.6,47.98 55.6,47.99 56.48,48.87 56.49,48.87 68.46,48.89 68.98,48.88 73.35,48.88 73.58,48.89 73.74,48.89 J2.42
P7.5
  Top 0.254: J2.41 | J2.41 74.18,46.34 | J2.41 69.79,46.34 63.65,40.2 57.79,40.2 57.6,40.02 U1.P41
P7.6
  Route2 0.254: U1.P40 56.6,40.71 56.6,45.21 57.32,45.93 62.62,45.93 62.64,45.91 68.84,45.91 70.93,43.81 73.34,43.81 J2.40
P7.7
  Route15 0.254: J2.39 71.19,41.27 69.12,43.34 61.63,43.34 59.94,44.98 59.94,46.62 59.13,47.48 55.26,47.48 52.02,44.25 52.02,39.86 52.63,39.25 53.52,39.25 53.56,39.21 U1.P39
P8.0
  Top 0.254: J2.38 74.08,38.73 74.05,38.75 74.01,38.71 U1.P38
P8.1
  Route2 0.254: U1.P37 56,38.21 56.6,37.61 56.6,31.92 57.54,30.98 68.9,30.98 74.11,36.19 J2.37
P8.2
  Route2 0.254: U1.P36 53.17,37.71 52.39,36.93 52.39,32.2 54.75,29.84 70.34,29.84 74.13,33.62 J2.36
P8.3
  Top 0.254: J2.35 69.75,31.11 63.66,37.2 57.74,37.2 57.71,37.23 57.7,37.21 U1.P35
P8.4
  Route15 0.254: U1.P34 56.01,36.71 56.6,36.11 56.6,31.39 59.42,28.57 73.83,28.57 73.9,28.49 73.98,28.57 J2.34
P8.5  (via drill 0.3)
  Route2 0.254: v51.8,30.4 56.2,26 73.77,26 73.8,26.03 J2.33
  Route15 0.254: U1.P33 51.98,36.21 51.27,35.5 51.27,30.93 v51.8,30.4
P8.6
  Top 0.254: J2.32 72.29,23.49 66.47,29.26 66.47,32.36 63.04,35.79 57.64,35.79 57.64,35.75 U1.P32
P8.7
  Route15 0.254: U1.P31 55.2,35.21 54.6,34.61 54.6,31.74 60.97,25.37 69.69,25.37 74.11,20.95 J2.31
P9.0
  Route15 0.254: U1.P30 52.84,34.71 52.29,34.16 52.29,32.18 66.05,18.41 J2.30
P9.1
  Top 0.254: J2.29 72.37,15.87 64.91,23.32 64.91,31.83 62.5,34.2 57.89,34.2 57.7,34.39 57.6,34.29 U1.P29
P9.2  (via drill 0.3)
  Top 0.254: U1.P28 55.6,30.74 v62.09,24.25
  Route2 0.254: v62.09,24.25 72.99,13.35 73.95,13.35 73.98,13.33 J2.28
P9.3  (via drill 0.3)
  Top 0.254: U1.P27 53.6,29.54 v62.5,20.64
  Route2 0.254: v62.5,20.64 62.5,20.59 72.3,10.79 J2.27 74.16,10.79
P9.4
  Top 0.254: J2.26 63.62,18.76 63.62,31.11 61.95,32.73 57.83,32.73 57.76,32.8 57.68,32.71 U1.P26
P9.5
  Top 0.254: 66.17,11.08 50.63,11.08 49.65,12.06 49.65,24.73 49.68,24.76 | 66.17,11.08 66.2,11.08 | 49.68,24.76 49.75,24.84 | 49.68,24.76 U1.P25 | 66.17,11.08 66.17,11.09 68.69,11.09 72.95,6.84 74.1,5.75 74.1,3.22 74.13,3.19 J1.25
P9.6  (via drill 0.3)
  Top 0.254: v59.18,18.15 v63.12,14.21
  Route2 0.254: U1.P24 50.56,26.76 v59.18,18.15 | v63.12,14.21 65.84,14.21 71.59,8.46 71.59,4.82 71.59,4.11 71.59,3.76 J1.24
P9.7  (via drill 0.3)
  Route2 0.254: U1.P23 49.66,28.76 54.82,23.61 v60.33,18.04
  Route15 0.254: v60.33,18.04 64.57,13.83 65.33,13.11 69.05,9.39 69.05,4.87 69.05,4.21 J1.23
P10.0
  Top 0.254: U1.P22 48.17,24.76 48.18,24.77 48.18,11.82 48.17,11.82 48.17,11.84 50.22,9.8 65.72,9.8 66.51,9.01 66.51,3.47 66.48,3.45 66.51,3.42 J1.22
P10.1  (via drill 0.3)
  Top 0.254: U1.P21 48.67,27.79 49.53,27.79 51.7,25.62 51.7,22.63 51.69,22.62 v51.69,14.4
  Route2 0.254: v51.69,14.4 52.55,13.54 52.55,2.67 53.34,1.9 62.74,1.9 63.48,2.67 63.67,2.86 J1.21
P10.2
  Route2 0.254: U1.P20 48.15,29.76 49.56,29.76 61.38,18.14 61.43,6.42 J1.20
P10.3
  Top 0.254: 46.66,24.76 46.67,24.77 | 46.66,24.76 U1.P19 | 46.66,24.76 46.65,24.75 46.65,11.73 50.07,8.25 55.86,8.25 58.22,8.26 58.88,7.57 58.88,3.38 58.89,3.37 J1.19
RST/NMI
  Top 0.254: JTAG.11 20.34,89.08 66.65,89.08 66.66,89.07 66.57,89.1 67.77,87.65 67.77,85.78 69.11,84.46 BOOTST.4 | U1.P100 26.49,32.71 25.14,31.37 25.14,31.29 25.13,31.29 24.59,30.76 23.09,29.3 16.49,22.7 16.49,16.17 15.44,15.12 15.44,11.01 15.44,9.61 | J4.100 13.07,8.25 12.99,8.18 C8.2 9.71,10.45 9.72,10.46 9.69,10.48 R5.1
  Top 0.305: J4.100 14.05,8.25 15.44,9.61
  Route15 0.254: JTAG.11 18.23,86.99 16.98,85.75 16.98,81.5 16.29,80.82 10.78,80.82 6.06,76.09 6.06,15.34 13.17,8.22 J4.100
TCK  (via drill 0.3)
  Top 0.254: U1.P99 31.7,32.42 28.19,28.88 24.93,28.88 17.8,21.77 v17.8,11.83
  Route2 0.254: J4.99 16.85,10.79 17.8,11.73 v17.8,11.83
  Route15 0.254: BOOTST.2 70.34,85.69 70.34,87.83 69.61,88.56 23.69,88.56 23.38,88.26 23.38,87.17 23.33,87.12 JTAG.7 23.33,86.97 22.09,85.72 22.09,80.23 21.37,79.52 11.37,79.52 7.58,75.74 7.58,16.2 12.99,10.79 J4.99
  Route15 0.406: BOOTST.2
TDI
  Top 0.254: U1.P97 29.65,34.26 28.65,34.26 28.65,34.25 27.83,33.43 25.94,33.43 25.67,33.16 25.41,32.92 25.39,32.92 15.53,23.05 15.53,16.45 15,15.92 13.17,15.92 J4.97
  Route15 0.254: JTAG.3 28.38,86.99 27.19,85.8 27.19,78.12 26.23,77.16 12.28,77.16 10.05,74.93 10.05,18.99 J4.97
TDO  (via drill 0.3)
  Top 0.254: U1.P96 32.71,33.7 32.71,32.27 28.57,28.13 25.79,28.13 25.17,28.15 18.85,21.82 v18.83,18.45
  Route2 0.254: J4.96 13.45,18.41 13.49,18.45 v18.83,18.45
  Route15 0.254: JTAG.1 29.7,85.75 29.7,77.11 28.87,76.27 12.54,76.27 11.04,74.77 11.04,20.54 J4.96
TMS  (via drill 0.3)
  Top 0.254: U1.P98 33.7,32.45 28.72,27.47 26.11,27.47 | v19.84,13.34 19.84,19.01 19.82,20.61 19.82,21.18 19.82,21.81 25.45,27.47 26.11,27.47 | 26.11,27.47 26.11,27.44
  Route2 0.254: J4.98 13.27,13.33 13.28,13.34 v19.84,13.34
  Route15 0.254: JTAG.5 24.62,85.75 24.62,79.62 23.38,78.38 11.8,78.38 8.85,75.43 8.85,17.65 J4.98
VCC  (via drill 0.3)
  Top 0.254: R11.2 52.05,83.94 52.01,83.99 51.98,83.97
  Top 0.406: v4.51,82.32 7.05,82.31 9.98,82.31 37.89,82.31 39.04,82.32 41.11,82.32 | 41.11,82.32 45.05,82.32 46.7,83.97 R10.2 | 41.11,82.32 JP3.2 | R10.2 52.01,83.97 52.04,83.93 R11.2 52.05,83.84 52.01,83.79 52.01,83.05 51.17,82.22 JP1.1 | R10.2
  Route2 0.406: v4.51,82.32 4.49,82.29 4.48,82.29 4.48,81.65 4.48,72.36 4.49,70.58 3.14,69.23 3.14,69.21 J5.1
  Bottom 0.254: J5.1 3.04,69.16
VREF  (via drill 0.3)
  Top 0.254: U1.P9 40.66,25.78 36.74,25.78 36.39,25.42 C5.2 C6.2 36.39,13.23 36.39,13.18 v33.49,10.28
  Route2 0.254: J1.9 v33.49,10.28
XI
  Top 0.254: R6.2 33.92,69.64 J3.65
XIN  (via drill 0.8 pad 0.3)
  Top 0.254: R6.1 C2.1 36.06,61.82 35.87,61.45 Q1.2 34.09,58.55 34.07,58.57 v33.93,58.57 33.93,58.55 33.86,58.48
  Route2 0.254: U1.P65 41.65,51.66 36.66,51.66 35.83,52.5 35.83,58.53 Q1.2
XO
  Top 0.254: R8.2 40.58,65.6 39.84,66.34 39.84,75.61 39.23,76.22 37.96,76.22 J3.66
XOUT  (via drill 0.8 pad 0.3)
  Top 0.254: R8.1 38.39,61.82 38.37,61.81 38.35,61.82 C1.1 38.3,58.6 38.29,58.59 38.29,58.57 | Q1.1 37.24,58.55 37.25,58.54 37.27,58.57 38.29,58.57 | 38.29,58.57 v39.02,58.57 39.02,56.95 42.15,53.82 42.15,52.93 U1.P66
XT2I  (via drill 0.3)
  Top 0.254: R12.2 14.37,39.94 14.31,40 3.9,40 3.14,39.24 3.14,24.38 v4.05,23.49
  Route2 0.254: v4.05,23.49 J4.94
XT2IN  (via drill 0.8 pad 0.3)
  Top 0.254: R12.1 19.22,38.03 19.24,38.02 19.23,38.01 C4.1 19.23,37.83 19.51,37.55 22.01,37.55 22.06,37.6 22.1,37.55 Q2.1 | Q2.1 22.18,37.62 22.18,37.63 v22.18,39.46 | Q2.1 25.14,37.55 26.99,35.71 U1.P94 | U1.P94
XT2O
  Top 0.254: R9.2 17.29,33.9 17.05,33.65 17.05,26.96 16.12,26.03 J4.93
XT2OUT  (via drill 0.8)
  Top 0.254: v22.18,34.35 Q2.2 22.15,36.26 19.56,36.26 C3.1 19.19,35.93 19.19,33.9 R9.1
  Route2 0.254: U1.P93 31.53,36.21 30.72,35.4 30.72,32.13 29.58,30.98 25.34,30.98 22.18,34.3 v22.18,34.35
  Bottom 0.254: v22.18,34.35 22.17,34.34 22.17,34.32
XTLGND1  (via drill 0.8 pad 0.3)
  Top 0.254: C1.2 38.3,64.06 37.13,65.23 v37.13,65.28 37.11,65.28 36.02,64.18 C2.2
  Route2 0.406: 35.78,65.25 38.47,65.25
  pour Route2: 40.75,66.12 34.09,66.12 32.72,64.76 32.74,54.93 33.56,54.1 40.66,54.1 41.55,54.93 41.55,65.39
XTLGND2  (via drill 0.8 pad 0.3)
  Top 0.406: C4.2 16.83,37.95 15.87,36.99 v15.87,36.96 15.87,36.95 16.89,35.93 C3.2
  Route2 0.406: 15.84,35.94 15.84,38.2
  pour Route2: 15.35,33.55 15.41,33.55 16.22,32.76 22.39,32.76 22.77,32.79 27.34,32.79 28.33,34.26 28.33,40.25 27.44,41.14 16.07,41.14 15.41,40.48 15.41,33.68

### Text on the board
tNames: Vcc | ext | int | MSP-TS430PZ100A | Rev.: 2.0 | 1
